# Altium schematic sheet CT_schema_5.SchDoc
size 221 x 258 mm
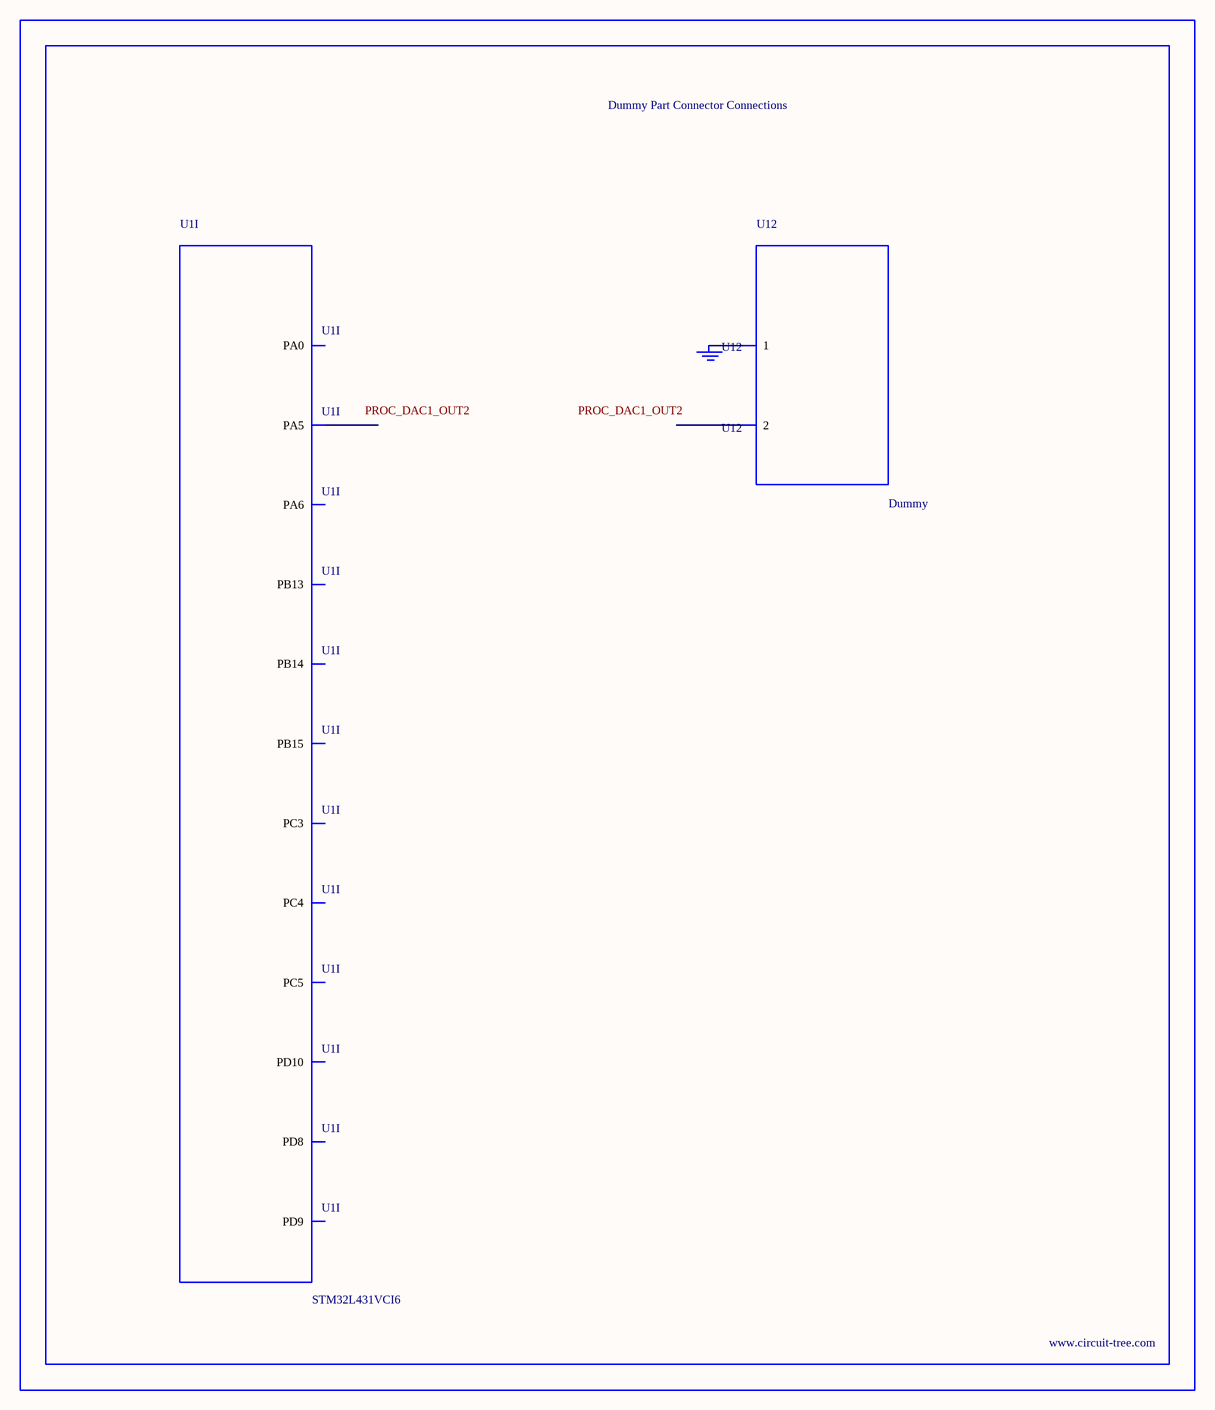
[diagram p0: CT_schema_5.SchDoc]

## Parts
BORDER4  (no value)
GND_INSTANCE_4_0  (no value)
U1  STM32L431VCI6  [UFBGA100]  (part I of 9)
U12  Dummy  [DUMMY_PACKAGE_132]

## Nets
NetGND_INSTANCE_4_0_0: GND_INSTANCE_4_0.0(GND) U12.1

Not connected (* = marked no-connect by the designer): U1 J12(PD10) K2(PC3) K4(PA5) K5(PC4) K8(PD9) K9(PD8) K10(PB15) K11(PB14) K12(PB13) L2(PA0) L4(PA6) L5(PC5); U12 2

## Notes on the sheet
- Labels drawn without touching a wire or pin: PROC_DAC1_OUT2

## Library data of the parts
BORDER4 = BORDER_PAGE4
GND_INSTANCE_4_0 = GND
